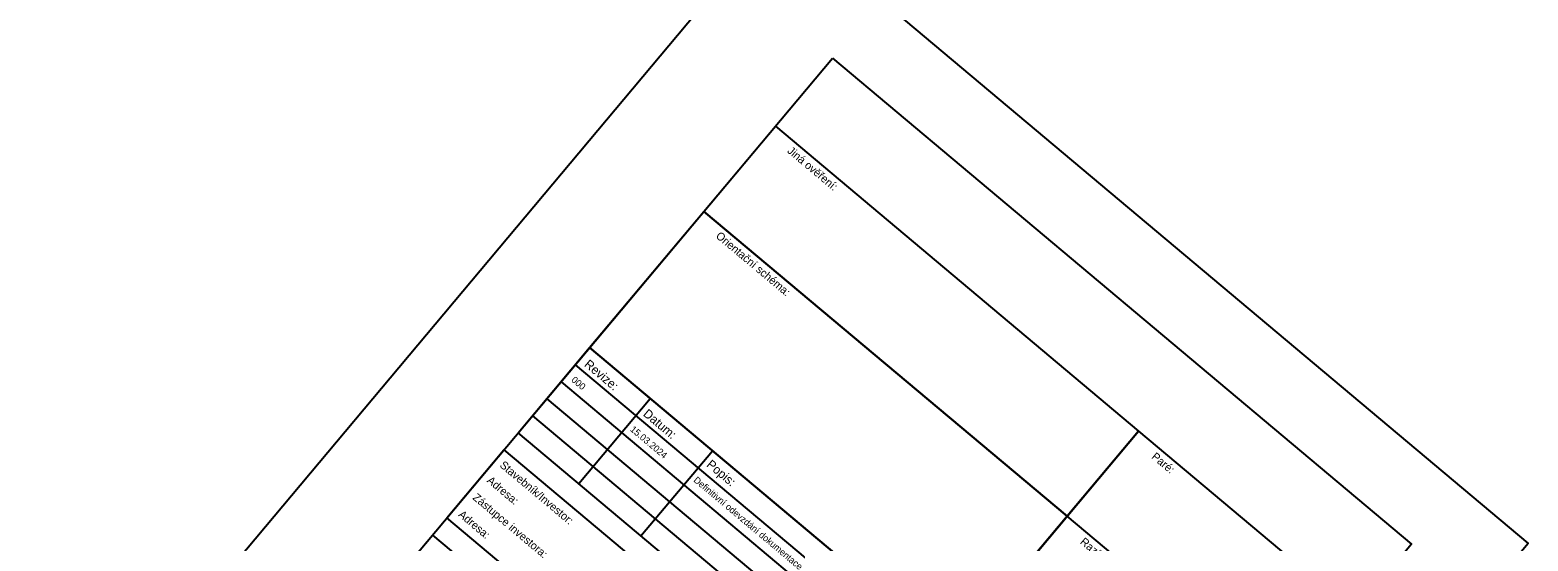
# Model space of a CAD drawing. Extents: x -653515 to -646779, y -1102358 to -1096033.
# Drawn here: x -650150 to -646779, y -1100078 to -1098928 of the extents above; entities that cross this region are included whole.
import ezdxf

# ---------------------------------------------------------------- set-up
doc = ezdxf.new("R2010")
doc.units = 0
for name, color, linetype in [('Default', 7, 'Continuous'), ('Oblast stavby', 7, 'Continuous'), ('pomocná - netisk 2', 7, 'Continuous'), ('Rozpiska_pola_3', 7, 'Continuous'), ('Rozpiska_pole_1', 7, 'Continuous'), ('Rozpiska_pole_2', 7, 'Continuous'), ('Rozpiska_pole_4', 7, 'Continuous'), ('Rozpiska_pole_5', 7, 'Continuous'), ('Rozpiska_pole_6', 7, 'Continuous')]:
    doc.layers.add(name, color=color, linetype=linetype)

msp = doc.modelspace()

# ---------------------------------------------------------------- linework, layer by layer
at = {"layer": 'Default'}
msp.add_line((-648073.6, -1100328.2), (-647655.8, -1099830.3), dxfattribs=at)
at = {"layer": 'Oblast stavby'}
msp.add_lwpolyline([(-650309.6, -1100867), (-653373.8, -1098295.9), (-651593.2, -1096173.9), (-648529.1, -1098745.1)], close=True, dxfattribs=at)
at = {"layer": 'pomocná - netisk 2'}
msp.add_lwpolyline([(-651605.6, -1096033), (-653514.6, -1098308.2), (-648688.6, -1102357.8), (-646779.5, -1100082.6)], close=True, dxfattribs=at)
at = {"layer": 'Rozpiska_pole_1'}
msp.add_lwpolyline([(-648344.2, -1098991.5), (-647042, -1100084.3), (-648745.4, -1102114.3), (-650047.6, -1101021.6)], close=True, dxfattribs=at)
at = {"layer": 'Rozpiska_pole_2'}
for points in [[(-648472.8, -1099144.7), (-647655.8, -1099830.3), (-647816.5, -1100021.8), (-648633.5, -1099336.3)], [(-648633.5, -1099336.3), (-647816.5, -1100021.8), (-648073.6, -1100328.2), (-648890.6, -1099642.7)], [(-647655.8, -1099830.3), (-647170.5, -1100237.5), (-647331.2, -1100429), (-647816.5, -1100021.8)], [(-647331.2, -1100429), (-647816.5, -1100021.8), (-648073.6, -1100328.2), (-647588.3, -1100735.4)]]:
    msp.add_lwpolyline(points, close=True, dxfattribs=at)
at = {"layer": 'Rozpiska_pole_4'}
for p, q in [((-648922.8, -1099681), (-647620.5, -1100773.7)), ((-648954.9, -1099719.3), (-647652.6, -1100812)), ((-648987, -1099757.6), (-647684.8, -1100850.3)), ((-648915.2, -1099948.4), (-648754.5, -1099756.9)), ((-649019.2, -1099795.9), (-647716.9, -1100888.6)), ((-648775.2, -1100065.9), (-648614.5, -1099874.4))]:
    msp.add_line(p, q, dxfattribs=at)
msp.add_lwpolyline([(-648890.6, -1099642.7), (-647588.3, -1100735.4), (-647749, -1100926.9), (-649051.3, -1099834.2)], close=True, dxfattribs=at)
at = {"layer": 'Rozpiska_pole_5'}
msp.add_lwpolyline([(-649083.5, -1099872.5), (-647781.2, -1100965.2), (-647909.7, -1101118.4), (-649212, -1100025.7)], close=True, dxfattribs=at)
at = {"layer": 'Rozpiska_pole_6'}
msp.add_lwpolyline([(-649244.2, -1100064), (-647941.9, -1101156.7), (-648199, -1101463.2), (-649501.3, -1100370.4)], close=True, dxfattribs=at)

# ---------------------------------------------------------------- texts
at = {"layer": 'Rozpiska_pola_3'}
for s, p in [('Paré:', (-647627.9, -1099890.3)), ('Razítko oprávněné osoby:', (-647788.6, -1100081.8))]:
    msp.add_text(s, height=18, rotation=320, dxfattribs=at).set_placement(p)
at = {"layer": 'Rozpiska_pole_2'}
for s, p in [('Jiná ověření:', (-648447.5, -1099202.5)), ('Orientační schéma:', (-648608.2, -1099394))]:
    msp.add_text(s, height=18, rotation=320, dxfattribs=at).set_placement(p)
at = {"layer": 'Rozpiska_pole_4'}
for s, height, p in [('Revize:', 20, (-648904.3, -1099683)), ('000', 15, (-648933.2, -1099717.5)), ('Datum:', 20, (-648771.8, -1099794.2)), ('15.03.2024', 15, (-648800.7, -1099828.7)), ('Popis:', 20, (-648629.2, -1099908.3)), ('Definitivní odevzdání dokumentace', 15, (-648658.2, -1099942.8))]:
    msp.add_text(s, height=height, rotation=320, dxfattribs=at).set_placement(p)
at = {"layer": 'Rozpiska_pole_5'}
for s, p in [('Stavebník/Investor:', (-649094.3, -1099909.4)), ('Adresa:', (-649123.2, -1099943.9)), ('Zástupce investora:', (-649155.3, -1099982.2)), ('Adresa:', (-649187.5, -1100020.5))]:
    msp.add_text(s, height=18, rotation=320, dxfattribs=at).set_placement(p)

doc.saveas('drawing.dxf')
